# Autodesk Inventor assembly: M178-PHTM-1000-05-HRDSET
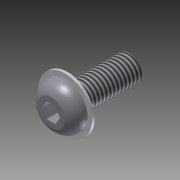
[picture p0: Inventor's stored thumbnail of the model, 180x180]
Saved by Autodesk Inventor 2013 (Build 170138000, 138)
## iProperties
Created: 2004-11
Part Number: M178-PHTM-1000-05-HRDSET
Document SubType Name: Assembly
Designer: Autodesk, Inc.
Manufacturer: Standard
Standards Organization: Custom
Description: PHANTOM, M10x25 SPRING HARDWARE SET
Mass: 23.1451 g
Surface Area: 21.5811 cm^2
Volume: 3.17882 cm^3
Density: 7.28104 g/cm^3
CAGE: 1LJX3
Dept. ID: Product Design
Description #2: ---
Finish #1: ---
Finish #2: ---
Material ID: ---
Project Number: ---
Author: Autodesk, Inc.
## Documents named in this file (4)
- Z:\_DATEN\Test Station\Components\M10x25-Spring Phantom.iam
- Z:\_DATEN\Test Station\Components\24-125-10.ipt
- Z:\_DATEN\Test Station\Components\24-708-10.ipt
- C:\Users\kelleyb.ADS\Desktop\Samples MIGRATED 2009 224 RTM_1\Standard Parts\Test Station Content\Fastners\2X-YYY-ZZ IPS Screws.ipt
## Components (2 placed, 2 different names)
1. 24-125-10:1
2. 24-708-10:1
